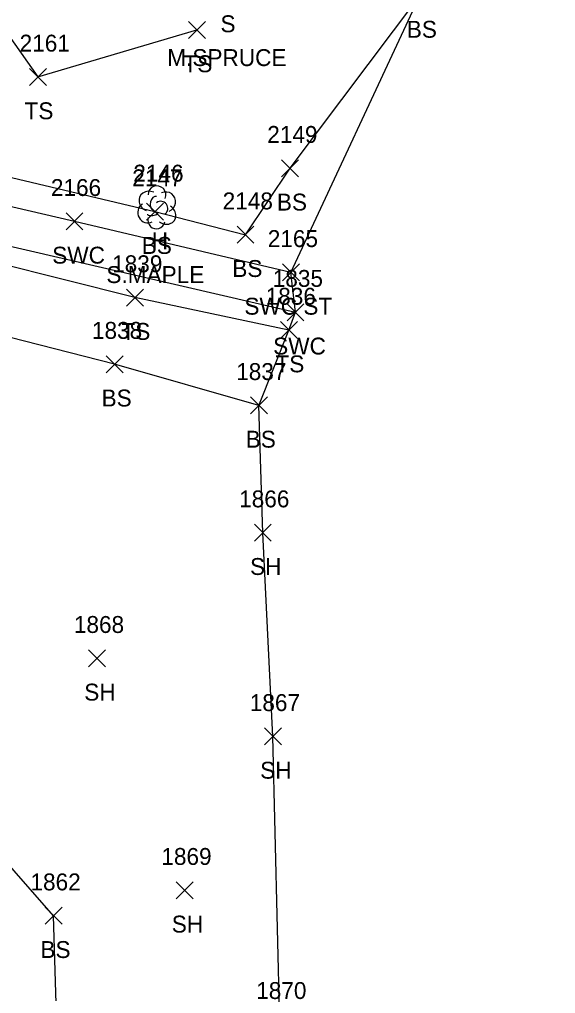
# Model space of a CAD drawing. Extents: x 1462668 to 1465147, y 550359 to 557351.
# Drawn here: x 1464851.4 to 1464914.9, y 552631.2 to 552746.4 of the extents above; entities that cross this region are included whole.
import ezdxf

# ---------------------------------------------------------------- set-up
doc = ezdxf.new("R2010")
doc.units = 0
for name, color, linetype in [('L_A', 7, 'Continuous'), ('L_C', 7, 'Continuous'), ('L_I', 7, 'Continuous'), ('L_TIC', 7, 'Continuous'), ('LELB', 7, 'Continuous'), ('Level 6', 7, 'Continuous'), ('LTD', 7, 'Continuous'), ('R_A', 7, 'Continuous'), ('R_I', 7, 'Continuous'), ('R_TIC', 7, 'Continuous'), ('RSW', 7, 'Continuous')]:
    doc.layers.add(name, color=color, linetype=linetype)

msp = doc.modelspace()

# ---------------------------------------------------------------- linework, layer by layer
at = {"layer": 'L_TIC'}
for points in [[(1464871.44, 552744.15), (1464873.44, 552746.15)], [(1464873.44, 552744.15), (1464871.44, 552746.15)], [(1464852.62, 552738.59), (1464854.62, 552740.59)], [(1464854.62, 552738.59), (1464852.62, 552740.59)], [(1464882.47, 552727.79), (1464884.47, 552729.79)], [(1464884.47, 552727.79), (1464882.47, 552729.79)], [(1464866.47, 552722.66), (1464868.47, 552724.66)], [(1464868.47, 552722.66), (1464866.47, 552724.66)], [(1464877.19, 552719.93), (1464879.19, 552721.93)], [(1464879.19, 552719.93), (1464877.19, 552721.93)], [(1464864.1, 552712.49), (1464866.1, 552714.49)], [(1464866.1, 552712.49), (1464864.1, 552714.49)], [(1464882.33, 552708.65), (1464884.33, 552710.65)], [(1464884.33, 552708.65), (1464882.33, 552710.65)], [(1464861.7, 552704.61), (1464863.7, 552706.61)], [(1464863.7, 552704.61), (1464861.7, 552706.61)], [(1464878.78, 552699.74), (1464880.78, 552701.74)], [(1464880.78, 552699.74), (1464878.78, 552701.74)], [(1464879.24, 552684.68), (1464881.24, 552686.68)], [(1464881.24, 552684.68), (1464879.24, 552686.68)], [(1464859.61, 552669.82), (1464861.61, 552671.82)], [(1464861.61, 552669.82), (1464859.61, 552671.82)], [(1464880.44, 552660.58), (1464882.44, 552662.58)], [(1464882.44, 552660.58), (1464880.44, 552662.58)], [(1464869.98, 552642.38), (1464871.98, 552644.38)], [(1464871.98, 552642.38), (1464869.98, 552644.38)], [(1464854.47, 552639.37), (1464856.47, 552641.37)], [(1464856.47, 552639.37), (1464854.47, 552641.37)]]:
    msp.add_lwpolyline(points, dxfattribs=at)
at = {"layer": 'LELB'}
for points in [[(1464875.43, 552806.2), (1464863.86, 552787.59), (1464848.84, 552770.46), (1464840.99, 552757.52), (1464853.62, 552739.59), (1464872.44, 552745.15)], [(1464828.56, 552752.39), (1464819.99, 552736.13), (1464831.31, 552732.24), (1464867.47, 552723.66), (1464878.19, 552720.93), (1464883.47, 552728.79), (1464898.85, 552749.23), (1464914.9, 552763.87)], [(1464883.33, 552709.65), (1464865.1, 552713.49), (1464840.21, 552719.75), (1464823.3, 552721.8), (1464810.42, 552723.95)], [(1464879.78, 552700.74), (1464862.7, 552705.61), (1464836.07, 552712.41), (1464822.03, 552711.23), (1464810.25, 552718.32), (1464801.52, 552701.91), (1464787.63, 552688.07), (1464797.02, 552670.88)], [(1464856, 552622.19), (1464855.47, 552640.37), (1464841.72, 552656.02), (1464819.81, 552676.19), (1464823.29, 552689.95)]]:
    msp.add_lwpolyline(points, dxfattribs=at)
at = {"layer": 'Level 6'}
msp.add_lwpolyline([(1464882.24, 552627.52), (1464881.44, 552661.58), (1464880.24, 552685.68), (1464879.78, 552700.74), (1464883.33, 552709.65), (1464884.11, 552711.76), (1464883.57, 552716.47), (1464898.85, 552749.23)], dxfattribs=at)
at = {"layer": 'LTD'}
msp.add_line((1464867.66, 552724.21), (1464867.66, 552724.21), dxfattribs=at)
msp.add_line((1464867.66, 552724.21), (1464867.66, 552724.21), dxfattribs=at)
msp.add_arc((1464867.71, 552725.65), 1.05, 335.5272, 180.9563, dxfattribs=at)
for centre, major_axis, ratio, start_param, end_param in [((1464866.87, 552724.88), (1.21, -0.51), 0.895232, 1.570796, 4.712389), ((1464867.45, 552724.67), (-0.208, -0.792), 0.645439, 3.141593, 6.283185), ((1464868.7, 552724.8), (-1.14, -0.48), 0.949671, 1.570796, 4.712389), ((1464866.58, 552723.51), (0.58, -1.04), 0.959034, 3.141593, 6.283185), ((1464868.16, 552724.05), (-0.5, 0.667), 0.989748, 3.141593, 6.283185), ((1464868.66, 552723.38), (-1.09, 0.79), 0.841452, 1.570796, 4.712389), ((1464867.2, 552723.46), (-0.625, -0.083), 0.423636, 0, 3.141593), ((1464867.66, 552722.71), (0.26, 1.06), 0.942809, 1.570796, 4.712389)]:
    msp.add_ellipse(centre, major_axis=major_axis, ratio=ratio, start_param=start_param, end_param=end_param, dxfattribs=at)
at = {"layer": 'R_TIC'}
for points in [[(1464856.95, 552721.51), (1464858.95, 552723.51)], [(1464858.95, 552721.51), (1464856.95, 552723.51)], [(1464882.57, 552715.47), (1464884.57, 552717.47)], [(1464884.57, 552715.47), (1464882.57, 552717.47)], [(1464883.11, 552710.76), (1464885.11, 552712.76)], [(1464885.11, 552710.76), (1464883.11, 552712.76)]]:
    msp.add_lwpolyline(points, dxfattribs=at)
at = {"layer": 'RSW'}
for points in [[(1464883.57, 552716.47), (1464857.95, 552722.51), (1464821.24, 552731), (1464815.23, 552732.85)], [(1464757.36, 552645.64), (1464754.47, 552647.95), (1464747.39, 552654.01), (1464767.97, 552677.6), (1464784.12, 552696.11), (1464787.62, 552700.03), (1464807.52, 552723.23), (1464811.99, 552728.74), (1464843.13, 552721.25), (1464884.11, 552711.76)]]:
    msp.add_lwpolyline(points, dxfattribs=at)

# ---------------------------------------------------------------- texts
at = {"layer": 'L_A'}
for s, p in [('S', (1464875.23, 552744.88)), ('BS', (1464897.29, 552744.23)), ('TS', (1464870.85, 552740.15)), ('TS', (1464852.03, 552734.59)), ('BS', (1464881.91, 552723.79)), ('H', (1464867.09, 552719.21)), ('BS', (1464865.91, 552718.66)), ('BS', (1464876.63, 552715.93)), ('TS', (1464863.51, 552708.49)), ('TS', (1464881.74, 552704.65)), ('BS', (1464861.15, 552700.61)), ('BS', (1464878.22, 552695.74)), ('SH', (1464878.73, 552680.68)), ('SH', (1464859.1, 552665.82)), ('SH', (1464879.93, 552656.58)), ('SH', (1464869.46, 552638.38)), ('BS', (1464853.91, 552635.37))]:
    msp.add_text(s, height=2, dxfattribs=at).set_placement(p)
at = {"layer": 'L_C'}
for s, p in [('M.SPRUCE', (1464868.93, 552740.88)), ('S.MAPLE', (1464861.72, 552715.21))]:
    msp.add_text(s, height=2, dxfattribs=at).set_placement(p)
at = {"layer": 'L_I'}
for s, p in [('2161', (1464851.45, 552742.59)), ('2149', (1464880.77, 552731.79)), ('2146', (1464864.91, 552727.21)), ('2147', (1464864.78, 552726.66)), ('2148', (1464875.49, 552723.93)), ('1839', (1464862.4, 552716.49)), ('1836', (1464880.58, 552712.65)), ('1838', (1464860.01, 552708.61)), ('1837', (1464877.09, 552703.74)), ('1866', (1464877.44, 552688.68)), ('1868', (1464857.87, 552673.82)), ('1867', (1464878.7, 552664.58)), ('1869', (1464868.23, 552646.38)), ('1862', (1464852.73, 552643.37)), ('1870', (1464879.46, 552630.52))]:
    msp.add_text(s, height=2, dxfattribs=at).set_placement(p)
at = {"layer": 'R_A'}
for s, p in [('SWC', (1464855.31, 552717.51)), ('SWC ST', (1464878.06, 552711.47)), ('SWC', (1464881.47, 552706.76))]:
    msp.add_text(s, height=2, dxfattribs=at).set_placement(p)
at = {"layer": 'R_I'}
for s, p in [('2166', (1464855.15, 552725.51)), ('2165', (1464880.83, 552719.47)), ('1835', (1464881.42, 552714.76))]:
    msp.add_text(s, height=2, dxfattribs=at).set_placement(p)

doc.saveas('drawing.dxf')
